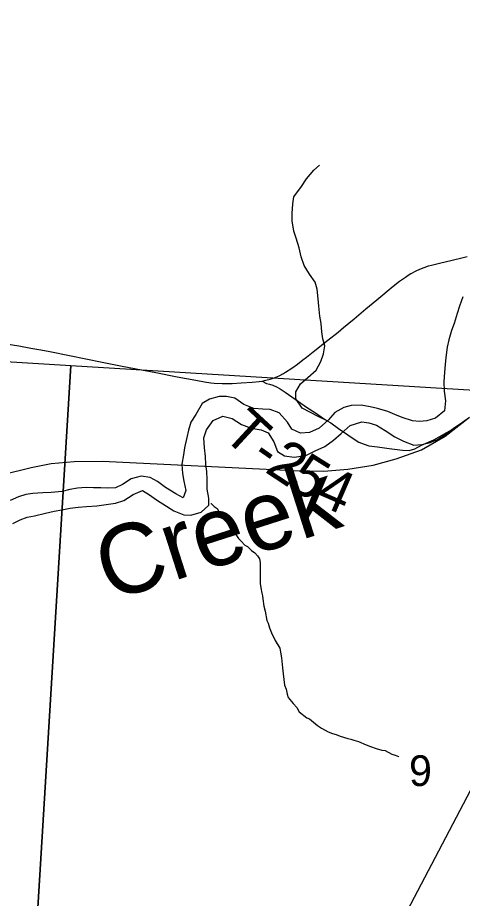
# Model space of a CAD drawing. Extents: x 0 to 34, y 0 to 22.
# Drawn here: x 5.436 to 6.043, y 18.818 to 20.019 of the extents above; entities that cross this region are included whole.
import ezdxf

# ---------------------------------------------------------------- set-up
doc = ezdxf.new("R2010")
doc.units = 0
for name, color, linetype in [('GM_X_County_Road', 7, 'Continuous'), ('GM_X_Minor_River', 7, 'Continuous'), ('GM_X_Minor_River_Text', 7, 'Continuous'), ('GM_X_Rail_Line', 7, 'Continuous'), ('GM_X_Section', 7, 'Continuous'), ('GM_X_Section_Text', 7, 'Continuous'), ('GM_X_State_Route', 7, 'Continuous'), ('GM_X_Township_Road', 7, 'Continuous'), ('GM_X_Township_Road_Text', 7, 'Continuous'), ('SH_Text', 7, 'Continuous')]:
    doc.layers.add(name, color=color, linetype=linetype)

msp = doc.modelspace()

# ---------------------------------------------------------------- linework, layer by layer
at = {"layer": 'GM_X_County_Road'}
for points in [[(5.7695, 19.5233), (5.7748, 19.5245), (5.7807, 19.526), (5.7861, 19.5277), (5.7927, 19.5306), (5.7986, 19.5338), (5.8016, 19.5355), (5.8099, 19.541), (5.8178, 19.5465), (5.8252, 19.5521), (5.8303, 19.5561), (5.8417, 19.5651), (5.8594, 19.5789), (5.8731, 19.5898), (5.8808, 19.5963), (5.8951, 19.6083), (5.9111, 19.6216), (5.9259, 19.6342), (5.9482, 19.6525), (5.9569, 19.6593), (5.9651, 19.6651), (5.9688, 19.6677), (5.9722, 19.6698), (5.9728, 19.6701), (5.9798, 19.6738), (5.9848, 19.6761), (5.9908, 19.6783), (5.9967, 19.6802), (6.0007, 19.6814), (6.0117, 19.6842), (6.0286, 19.6881), (6.0422, 19.6911), (6.0494, 19.693)], [(5.3849, 19.5794), (5.4027, 19.5767), (5.4207, 19.574), (5.4379, 19.5712), (5.4541, 19.5684), (5.468, 19.5657), (5.4802, 19.5637), (5.5068, 19.5582), (5.5292, 19.5536)], [(5.5292, 19.5536), (5.5515, 19.549), (5.5766, 19.5442), (5.5978, 19.5401), (5.6246, 19.535), (5.6539, 19.5291), (5.679, 19.5245), (5.691, 19.5222), (5.6996, 19.5211), (5.7044, 19.5204), (5.7153, 19.5199), (5.7286, 19.5202), (5.7408, 19.5208), (5.7558, 19.5218), (5.7657, 19.5227), (5.7695, 19.5233)]]:
    msp.add_lwpolyline(points, dxfattribs=at)
at = {"layer": 'GM_X_Minor_River'}
for points in [[(5.8582, 19.4689), (5.8452, 19.4753), (5.8354, 19.4803), (5.824, 19.4865), (5.8154, 19.4991), (5.8155, 19.5085), (5.822, 19.5195), (5.8319, 19.5282), (5.8433, 19.5383), (5.8495, 19.5501), (5.8533, 19.5603), (5.8553, 19.5713), (5.8523, 19.5808), (5.8509, 19.5906), (5.8502, 19.6016), (5.8484, 19.6119), (5.847, 19.6256), (5.8459, 19.6354), (5.8445, 19.6484), (5.8419, 19.6582), (5.8344, 19.6689), (5.8269, 19.6811), (5.8228, 19.6929), (5.8199, 19.7051), (5.8162, 19.718), (5.8128, 19.7279), (5.8107, 19.7419), (5.8107, 19.7518), (5.8116, 19.7651), (5.8128, 19.7745), (5.8231, 19.7885), (5.83, 19.7991), (5.8403, 19.8108), (5.8479, 19.8176)], [(6.0432, 19.6383), (6.039, 19.6253), (6.0356, 19.6155)], [(6.0356, 19.6155), (6.0314, 19.6018), (6.028, 19.5923), (6.0242, 19.5797), (6.0219, 19.5695), (6.02, 19.5554), (6.0192, 19.5459), (6.0184, 19.5356), (6.0173, 19.5223), (6.018, 19.5094), (6.0196, 19.4965), (6.0184, 19.4828), (6.0062, 19.4729), (5.9941, 19.4691), (5.9842, 19.4684), (5.9747, 19.4691), (5.9606, 19.4737), (5.9507, 19.4779), (5.9409, 19.4817), (5.9268, 19.4859), (5.9169, 19.4882), (5.9048, 19.4905), (5.8911, 19.4901), (5.8812, 19.4871), (5.8687, 19.4806), (5.8599, 19.4704), (5.8474, 19.459), (5.8344, 19.4533), (5.8219, 19.4525), (5.8101, 19.4579), (5.804, 19.4674), (5.793, 19.4799), (5.7805, 19.4845), (5.7706, 19.4849), (5.7581, 19.4861), (5.7448, 19.4914), (5.7322, 19.5001), (5.7208, 19.5024), (5.7109, 19.5024), (5.698, 19.4986), (5.6877, 19.4926), (5.679, 19.4778), (5.6725, 19.4675), (5.6691, 19.4565), (5.6668, 19.4466), (5.6638, 19.4325), (5.6622, 19.423), (5.6603, 19.4101), (5.6611, 19.3972), (5.663, 19.3869), (5.6656, 19.374), (5.6618, 19.3641), (5.6519, 19.3698), (5.6379, 19.3782), (5.6269, 19.3862), (5.617, 19.3919), (5.6044, 19.3938), (5.5911, 19.39), (5.579, 19.3824), (5.5695, 19.3779), (5.5592, 19.3775), (5.5497, 19.3779), (5.5398, 19.3779), (5.5296, 19.3783), (5.5178, 19.3775), (5.5075, 19.3753), (5.4969, 19.373), (5.4817, 19.3715), (5.4703, 19.3711), (5.457, 19.37), (5.4475, 19.3685), (5.4372, 19.3654), (5.4258, 19.3605)], [(5.4295, 19.3292), (5.4394, 19.3341), (5.4493, 19.3376), (5.4592, 19.3398), (5.474, 19.3432), (5.4858, 19.3459), (5.4964, 19.3478), (5.5078, 19.3501), (5.5188, 19.3516), (5.5302, 19.3523), (5.5443, 19.3531), (5.5569, 19.355), (5.5698, 19.3568), (5.5808, 19.3603), (5.5937, 19.3686), (5.6063, 19.3743), (5.6162, 19.3682), (5.6257, 19.3614), (5.6393, 19.3526), (5.6492, 19.3465), (5.6629, 19.3412), (5.6724, 19.3404), (5.6865, 19.3446), (5.6967, 19.3541), (5.6971, 19.3636), (5.6948, 19.3761), (5.6948, 19.3891), (5.6941, 19.4001), (5.693, 19.4096), (5.6922, 19.4206), (5.6911, 19.4324), (5.6903, 19.4461), (5.6938, 19.4567), (5.7029, 19.4696), (5.7162, 19.4757), (5.7287, 19.4723), (5.7416, 19.4643), (5.7546, 19.459), (5.7682, 19.457), (5.7777, 19.4528), (5.7857, 19.4407), (5.7906, 19.4274), (5.8001, 19.4213), (5.8134, 19.4194), (5.8294, 19.422), (5.842, 19.4281), (5.8553, 19.4342), (5.8671, 19.4429), (5.8773, 19.452), (5.8895, 19.4626), (5.9058, 19.4679), (5.9153, 19.4664), (5.9256, 19.4634), (5.9374, 19.4561), (5.9507, 19.4474), (5.9625, 19.4413), (5.9765, 19.436), (5.9872, 19.4367), (5.9986, 19.4394), (6.0088, 19.4435), (6.0187, 19.45), (6.032, 19.4602), (6.043, 19.4675)], [(5.6997, 19.3566), (5.7002, 19.3563), (5.7044, 19.3525), (5.7081, 19.3498), (5.7104, 19.3456), (5.7149, 19.3417), (5.719, 19.336), (5.7231, 19.3298), (5.7268, 19.3245), (5.7313, 19.3179), (5.7339, 19.3141), (5.7372, 19.3087), (5.741, 19.3049), (5.7459, 19.2995), (5.7496, 19.2976), (5.7553, 19.2922), (5.7598, 19.2891), (5.7635, 19.2849), (5.7661, 19.281), (5.7668, 19.2761), (5.7671, 19.2631), (5.7669, 19.2476), (5.768, 19.2415), (5.7694, 19.2342), (5.7701, 19.2304), (5.7704, 19.2266), (5.7718, 19.2167), (5.7737, 19.2095), (5.7762, 19.1969), (5.778, 19.1931), (5.7798, 19.187), (5.7824, 19.1801), (5.7872, 19.1698), (5.7936, 19.1591), (5.7946, 19.1537), (5.7961, 19.1461), (5.7971, 19.137), (5.7974, 19.1324), (5.7981, 19.1244), (5.8002, 19.1088), (5.8024, 19.1035), (5.8038, 19.0963), (5.8053, 19.0921), (5.812, 19.0836), (5.8169, 19.0782), (5.8203, 19.0725), (5.8304, 19.0644), (5.8342, 19.0628), (5.8451, 19.0539), (5.8507, 19.0501), (5.8598, 19.045), (5.8654, 19.0427), (5.8704, 19.0415), (5.876, 19.0391), (5.8866, 19.0359), (5.8904, 19.0351), (5.8945, 19.0336), (5.901, 19.0319), (5.9115, 19.0276), (5.9172, 19.0253), (5.9251, 19.0225), (5.9327, 19.0201), (5.9373, 19.0197), (5.9467, 19.0146), (5.9512, 19.0135), (5.9554, 19.0115), (5.956, 19.0112)]]:
    msp.add_lwpolyline(points, dxfattribs=at)
at = {"layer": 'GM_X_Rail_Line'}
msp.add_lwpolyline([(5.416, 19.3958), (5.4546, 19.4055), (5.482, 19.4111), (5.5134, 19.4135), (5.552, 19.4143), (5.8126, 19.4015), (5.8536, 19.4006), (5.8866, 19.4031), (5.9212, 19.4087), (5.9525, 19.4175), (5.9871, 19.4296), (6.0193, 19.4481), (6.0523, 19.4739)], dxfattribs=at)
at = {"layer": 'GM_X_Section'}
for points in [[(4.4823, 19.6076), (5.5089, 19.5445), (5.4469, 18.529), (4.4314, 18.5943)], [(5.5089, 19.5445), (6.5282, 19.4822), (6.4594, 18.4632), (5.4469, 18.529)]]:
    msp.add_lwpolyline(points, close=True, dxfattribs=at)
at = {"layer": 'GM_X_State_Route'}
for points in [[(5.7695, 19.5233), (5.7748, 19.5245), (5.7807, 19.526), (5.7861, 19.5277), (5.7927, 19.5306), (5.7986, 19.5338), (5.8016, 19.5355), (5.8099, 19.541), (5.8178, 19.5465), (5.8252, 19.5521), (5.8303, 19.5561), (5.8417, 19.5651), (5.8594, 19.5789), (5.8731, 19.5898), (5.8808, 19.5963), (5.8951, 19.6083), (5.9111, 19.6216), (5.9259, 19.6342), (5.9482, 19.6525), (5.9569, 19.6593), (5.9651, 19.6651), (5.9688, 19.6677), (5.9722, 19.6698), (5.9728, 19.6701), (5.9798, 19.6738), (5.9848, 19.6761), (5.9908, 19.6783), (5.9967, 19.6802), (6.0007, 19.6814), (6.0117, 19.6842), (6.0286, 19.6881), (6.0422, 19.6911), (6.0494, 19.693)], [(5.3849, 19.5794), (5.4027, 19.5767), (5.4207, 19.574), (5.4379, 19.5712), (5.4541, 19.5684), (5.468, 19.5657), (5.4802, 19.5637), (5.5068, 19.5582), (5.5292, 19.5536)], [(5.5292, 19.5536), (5.5515, 19.549), (5.5766, 19.5442), (5.5978, 19.5401), (5.6246, 19.535), (5.6539, 19.5291), (5.679, 19.5245), (5.691, 19.5222), (5.6996, 19.5211), (5.7044, 19.5204), (5.7153, 19.5199), (5.7286, 19.5202), (5.7408, 19.5208), (5.7558, 19.5218), (5.7657, 19.5227), (5.7695, 19.5233)]]:
    msp.add_lwpolyline(points, dxfattribs=at)
at = {"layer": 'GM_X_Township_Road'}
for points in [[(5.3849, 19.5794), (5.4027, 19.5767), (5.4207, 19.574), (5.4379, 19.5712), (5.4541, 19.5684), (5.468, 19.5657), (5.4802, 19.5637), (5.5068, 19.5582), (5.5292, 19.5536)], [(5.5292, 19.5536), (5.5515, 19.549), (5.5766, 19.5442), (5.5978, 19.5401), (5.6246, 19.535), (5.6539, 19.5291), (5.679, 19.5245), (5.691, 19.5222), (5.6996, 19.5211), (5.7044, 19.5204), (5.7153, 19.5199), (5.7286, 19.5202), (5.7408, 19.5208), (5.7558, 19.5218), (5.7657, 19.5227), (5.7695, 19.5233)], [(5.7695, 19.5233), (5.7754, 19.52), (5.7795, 19.5193), (5.7842, 19.5178), (5.7893, 19.5155), (5.7942, 19.5126), (5.8008, 19.5081), (5.8102, 19.5018), (5.819, 19.4955), (5.8302, 19.4877), (5.8424, 19.48), (5.85, 19.4747), (5.8585, 19.469), (5.8631, 19.4665), (5.8739, 19.4587), (5.8866, 19.45), (5.8951, 19.444), (5.9015, 19.4401), (5.9087, 19.4371), (5.915, 19.435), (5.927, 19.4335), (5.9429, 19.4312), (5.9612, 19.4291), (5.9702, 19.4286), (5.9779, 19.4309), (5.9871, 19.4358), (6.0036, 19.4433), (6.0286, 19.4573), (6.0525, 19.4739)]]:
    msp.add_lwpolyline(points, dxfattribs=at)
at = {"layer": 'SH_Text'}
msp.add_lwpolyline([(7.0694, 20.091), (7.0694, 20.9), (5.2191, 17.3772)], close=True, dxfattribs=at)

# ---------------------------------------------------------------- texts
at = {"layer": 'GM_X_Minor_River_Text'}
msp.add_text('Creek', height=0.09469, rotation=17.799, dxfattribs=at).set_placement((5.561, 19.2225))
at = {"layer": 'GM_X_Section_Text'}
msp.add_text('9', height=0.0419, rotation=0, dxfattribs=at).set_placement((5.97, 18.9713))
at = {"layer": 'GM_X_Township_Road_Text'}
for s, rotation, p in [('T', 317.2658, (5.7136, 19.4486)), ('2', 326.4468, (5.7718, 19.4004)), ('-', 325.3825, (5.7516, 19.4143)), ('5', 328.0685, (5.8024, 19.3801)), ('4', 336.5055, (5.8402, 19.3573))]:
    msp.add_text(s, height=0.0568, rotation=rotation, dxfattribs=at).set_placement(p)

doc.saveas('drawing.dxf')
